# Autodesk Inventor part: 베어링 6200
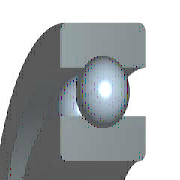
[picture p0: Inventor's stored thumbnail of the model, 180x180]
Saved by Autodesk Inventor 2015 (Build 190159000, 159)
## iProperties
Created: 2012-02
Part Number: 베어링 6200
Material: 강철, 연강
Description: 깊은 그루브 볼 베어링
Document SubType Name: Modeling
Standard: KS B 2023
Designer: mduedu
Standards Organization: KS
Language: ko-KR
Size Designation: 6200 - 10 x 30 x 9
Categories: <MemberInstance><Categories><Category DisplayName="샤프트 부품" InternalName="7f7aeb1f-a693-4053-b835-cee3144e0d98" Mnemonic="SHFT"><Category DisplayName="베어링" Inter
Density: 1 g/cm^3
Appearance: 노란색
IsCustomPart: 1
Author: mduedu
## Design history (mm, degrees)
sketch "스케치" dims "d0" = 5.2 (= -0.26 x WD + 0.26 x BD)
  geometry: L1 (1.9, 10)-(7.1, 10); L2 (4.5, 10)-(4.5, 7.4); L3 (4.5, 10)-(4.5, 12.6); L4 (2.568, 8.26)-(0, 8.26); L5 (0, 5)-(9, 5); L6 (2.568, 11.74)-(0, 11.74); L7 (0, 15)-(9, 15); L8 (9, 5)-(9, 8.26); L9 (6.432, 8.26)-(9, 8.26); L10 (6.432, 11.74)-(9, 11.74); L11 (9, 15)-(9, 11.74); L12 (-1.4, 0)-(8.4, 0) reference; L13 (0, -0.3)-(0, 5.3) reference
  constraints: 22 end point, 4 point on line, 2 collinear, 2 perpendicular, 2 symmetric about line, 1 midpoint, 1 parallel, 14 other
  dimensions: "d9" = 10 diameter of L5 L12 (= WD); "d11" = 30 diameter of L7 L12 (= BD); "d12" = 9 distance between parallel lines of L8 L13 (= KB); "d13" = 16.52 diameter of L9 L12 (= 0.326 x BD + 0.674 x WD)
revolve "본체" stored, may be unused: angle "d6" = 90 deg
revolve "볼" stored, may be unused: angle "d7" = 90 deg
pattern_circular "IDS_ARRAYBALL[SIMPL:T]" dims angle "d3" = 360 deg
body "Solid1"
fillet "모깎기1" dims "d1" = 0.6 (= KRS)
other parameters: "WD" = 10 [user parameter; used in 5 equation terms], "BD" = 30 [user parameter; used in 5 equation terms], "KB" = 9 [user parameter; used in 1 equation term], "KRS" = 0.6 [user parameter; used in 1 equation term], "d4" = 0, "d5" = 0, "d8" = 0, "d14" = 0, "d15" = 0, "BBA" = 0 [user parameter], "BC0" = 2360000 [user parameter], "BC" = 5070000 [user parameter], "BR" = 15 (= 0.5 x BD) [user parameter], "WR" = 5 (= 0.5 x WD) [user parameter]
